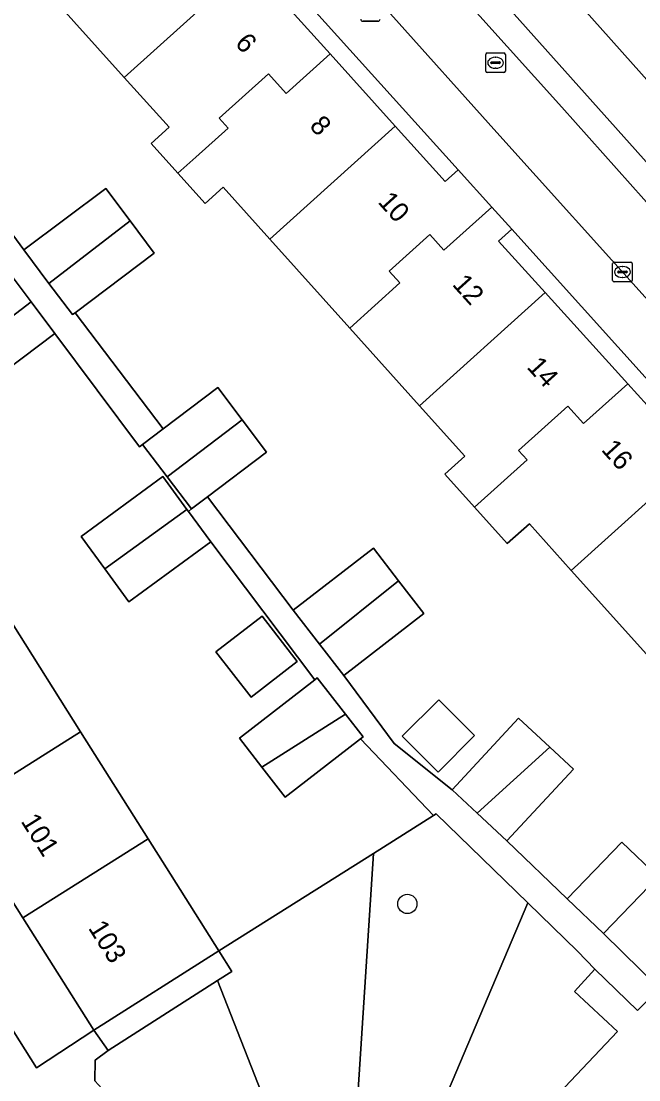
# Model space of a CAD drawing. Extents: x 162344 to 162869, y 381217 to 381818.
# Drawn here: x 162627.4 to 162658.9, y 381421.8 to 381475.8 of the extents above; entities that cross this region are included whole.
import ezdxf

# ---------------------------------------------------------------- set-up
doc = ezdxf.new("R2010")
doc.units = 0
for name, color, linetype in [('IMGEO_Boom', 7, 'Continuous'), ('IMGEO_Erf', 7, 'Continuous'), ('IMGEO_Groenvoorziening', 7, 'Continuous'), ('IMGEO_Kolk', 7, 'Continuous'), ('IMGEO_Lichtmast', 7, 'Continuous'), ('IMGEO_Pand', 7, 'Continuous'), ('IMGEO_Pand_nummerreeks', 7, 'Continuous'), ('IMGEO_Parkeervlak_open', 7, 'Continuous'), ('IMGEO_Rijbaan_lokaal_gesloten', 7, 'Continuous'), ('IMGEO_Rioolput', 7, 'Continuous'), ('IMGEO_Voetpad_open', 7, 'Continuous')]:
    doc.layers.add(name, color=color, linetype=linetype)

msp = doc.modelspace()

# ---------------------------------------------------------------- linework, layer by layer
at = {"layer": 'IMGEO_Boom'}
msp.add_circle((162647.119, 381430.789), 0.489, dxfattribs=at)
at = {"layer": 'IMGEO_Erf'}
for points in [[(162635.433, 381499.549), (162682.655, 381446.622)], [(162659.46, 381443.343), (162655.467, 381447.783), (162653.336, 381450.153), (162652.212, 381449.143), (162650.545, 381450.997), (162649.034, 381452.678), (162650.051, 381453.593), (162647.738, 381456.165), (162644.18, 381460.122), (162640.102, 381464.657), (162637.728, 381467.296), (162636.815, 381466.473), (162635.425, 381468.013), (162634.056, 381469.531), (162634.973, 381470.359), (162632.692, 381472.896), (162628.767, 381477.262)], [(162623.306, 381469.905), (162627.567, 381464.113), (162631.754, 381467.228), (162632.988, 381465.584), (162634.221, 381463.94), (162630.18, 381460.909), (162634.669, 381454.985), (162637.454, 381457.092), (162638.698, 381455.448), (162639.942, 381453.804), (162636.929, 381451.525), (162641.302, 381445.756), (162645.389, 381448.911), (162646.674, 381447.247), (162647.959, 381445.583), (162643.872, 381442.428), (162646.45, 381438.958), (162649.395, 381436.598), (162652.784, 381440.256), (162654.386, 381438.771), (162655.584, 381437.661), (162652.194, 381434.003), (162655.266, 381431.048), (162658.04, 381433.93), (162659.894, 381432.164), (162657.12, 381429.282), (162659.964, 381426.485)], [(162626.971, 381445.09), (162630.46, 381439.564), (162633.906, 381434.108), (162634.845, 381432.62), (162637.515, 381428.392), (162645.386, 381433.36), (162648.441, 381435.288), (162644.726, 381439.195), (162640.889, 381436.221), (162639.694, 381437.762), (162638.556, 381439.23), (162642.404, 381442.212), (162637.095, 381449.232), (162632.925, 381446.177), (162631.695, 381447.856), (162630.487, 381449.505), (162634.657, 381452.559), (162635.881, 381450.889), (162635.955, 381450.788), (162636.115, 381450.909), (162634.876, 381452.545), (162633.627, 381454.197), (162633.466, 381454.067), (162629.15, 381459.84), (162625.032, 381456.764)]]:
    msp.add_lwpolyline(points, dxfattribs=at)
for points in [[(162637.412, 381481.823), (162636.743, 381481.221), (162639.073, 381478.639), (162643.182, 381474.087), (162646.497, 381470.414), (162649.049, 381467.586), (162649.711, 381468.182)], [(162600.252, 381466.808), (162628.211, 381422.438), (162631.131, 381424.361), (162627.522, 381430.077), (162624.077, 381435.533), (162620.587, 381441.059), (162617.109, 381446.568), (162613.625, 381452.085), (162610.21, 381457.494), (162606.701, 381463.05), (162603.166, 381468.649)], [(162652.435, 381465.161), (162651.766, 381464.559), (162654.145, 381461.932), (162658.353, 381457.286), (162661.798, 381453.482), (162664.299, 381450.721), (162664.937, 381451.295)], [(162637.359, 381443.639), (162639.712, 381445.456), (162641.502, 381443.138), (162639.149, 381441.321)], [(162648.714, 381441.192), (162650.543, 381439.364), (162648.681, 381437.501), (162646.852, 381439.33)]]:
    msp.add_lwpolyline(points, close=True, dxfattribs=at)
at = {"layer": 'IMGEO_Groenvoorziening'}
for points in [[(162653.252, 381430.844), (162648.583, 381435.378), (162648.441, 381435.288), (162645.386, 381433.36), (162644.195, 381415.034)], [(162645.386, 381433.36), (162637.515, 381428.392), (162638.171, 381427.354), (162637.447, 381426.89), (162642.232, 381414.68)], [(162644.195, 381415.034), (162645.386, 381433.36)], [(162646.345, 381414.52), (162653.252, 381430.844)], [(162657.831, 381424.284), (162655.633, 381426.331), (162656.668, 381427.458), (162655.791, 381428.379), (162653.252, 381430.844), (162646.345, 381414.52)], [(162637.447, 381426.89), (162631.866, 381423.318), (162631.213, 381422.825), (162631.192, 381421.776), (162633.611, 381419.13), (162634.944, 381419.82), (162638.882, 381415.568), (162640.632, 381413.679)], [(162642.232, 381414.68), (162637.447, 381426.89)], [(162647.681, 381413.583), (162657.831, 381424.284)]]:
    msp.add_lwpolyline(points, dxfattribs=at)
at = {"layer": 'IMGEO_Kolk'}
for p, q in [((162657.58, 381462.556), (162657.58, 381463.408)), ((162657.655, 381463.482), (162658.507, 381463.482)), ((162658.068, 381463.262), (162658.093, 381463.262)), ((162658.581, 381463.408), (162658.581, 381462.556)), ((162657.839, 381462.976), (162657.839, 381462.988)), ((162658.277, 381462.939), (162657.879, 381462.939)), ((162657.882, 381463.025), (162658.28, 381463.025)), ((162658.091, 381462.702), (162658.066, 381462.702)), ((162658.323, 381462.988), (162658.323, 381462.976)), ((162658.507, 381462.482), (162657.655, 381462.482))]:
    msp.add_line(p, q, dxfattribs=at)
for points in [[(162657.58, 381462.556), (162657.58, 381463.408)], [(162657.655, 381463.482), (162658.507, 381463.482)], [(162658.581, 381463.408), (162658.581, 381462.556)], [(162658.507, 381462.482), (162657.655, 381462.482)]]:
    msp.add_lwpolyline(points, dxfattribs=at)
for centre, radius, start, end in [((162657.657, 381463.406), 0.0765, 91.552, 178.448), ((162657.657, 381463.406), 0.0765, 91.552, 178.448), ((162658.505, 381463.406), 0.0765, 1.552, 88.448), ((162658.505, 381463.406), 0.0765, 1.552, 88.448), ((162657.657, 381462.558), 0.0765, 181.552, 268.448), ((162657.657, 381462.558), 0.0765, 181.552, 268.448), ((162657.879, 381462.985), 0.0403, 85.8775, 175.7526), ((162657.876, 381462.975), 0.0366, 178.938, 274.7102), ((162658.28, 381462.982), 0.043, 264.8664, 352.4533), ((162658.284, 381462.987), 0.0386, 1.7309, 96.639), ((162658.505, 381462.558), 0.0765, 271.552, 358.448), ((162658.505, 381462.558), 0.0765, 271.552, 358.448)]:
    msp.add_arc(centre, radius, start, end, dxfattribs=at)
for centre, major_axis, ratio, start_param, end_param in [((162658.067, 381462.982), (-0.387, 0.002), 0.722429, 4.712389, 7.853982), ((162658.092, 381462.982), (-0.39, 0.002), 0.717154, 1.570796, 4.712389)]:
    msp.add_ellipse(centre, major_axis=major_axis, ratio=ratio, start_param=start_param, end_param=end_param, dxfattribs=at)
at = {"layer": 'IMGEO_Lichtmast'}
for p, q in [((162645.63, 381475.758), (162644.84, 381475.758)), ((162644.84, 381475.758), (162645.63, 381475.758))]:
    msp.add_line(p, q, dxfattribs=at)
for centre, start, end in [((162644.84, 381475.858), 180, 270), ((162644.84, 381475.858), 180, 270), ((162645.63, 381475.858), 270, 0), ((162645.63, 381475.858), 270, 0)]:
    msp.add_arc(centre, 0.1, start, end, dxfattribs=at)
at = {"layer": 'IMGEO_Pand'}
for points in [[(162628.767, 381477.262), (162632.692, 381472.896), (162639.073, 381478.639), (162636.743, 381481.221), (162637.412, 381481.823), (162635.981, 381483.41), (162633.538, 381481.207), (162632.82, 381482.003), (162630.756, 381480.142), (162631.297, 381479.542)], [(162643.182, 381474.087), (162639.073, 381478.639), (162632.692, 381472.896), (162634.973, 381470.359), (162634.056, 381469.531), (162635.425, 381468.013), (162636.341, 381468.839), (162637.977, 381470.315), (162637.529, 381470.812), (162640.038, 381473.074), (162640.944, 381472.069)], [(162643.182, 381474.087), (162640.944, 381472.069), (162640.038, 381473.074), (162637.529, 381470.812), (162637.977, 381470.315), (162636.341, 381468.839), (162635.425, 381468.013), (162636.815, 381466.473), (162637.728, 381467.296), (162640.102, 381464.657), (162646.497, 381470.414)], [(162646.497, 381470.414), (162640.102, 381464.657), (162644.18, 381460.122), (162646.732, 381462.422), (162646.191, 381463.022), (162648.255, 381464.883), (162648.973, 381464.087), (162651.417, 381466.29), (162649.711, 381468.182), (162649.049, 381467.586)], [(162632.988, 381465.584), (162631.754, 381467.228), (162627.567, 381464.113), (162628.854, 381462.4)], [(162654.145, 381461.932), (162651.766, 381464.559), (162652.435, 381465.161), (162651.417, 381466.29), (162648.973, 381464.087), (162648.255, 381464.883), (162646.191, 381463.022), (162646.732, 381462.422), (162644.18, 381460.122), (162647.738, 381456.165)], [(162632.988, 381465.584), (162628.854, 381462.4), (162630.047, 381460.809), (162630.18, 381460.909), (162634.221, 381463.94)], [(162627.939, 381461.461), (162626.727, 381463.083), (162622.609, 381460.007), (162623.851, 381458.345)], [(162629.15, 381459.84), (162627.939, 381461.461), (162623.851, 381458.345), (162625.032, 381456.764)], [(162650.545, 381450.997), (162653.22, 381453.408), (162652.785, 381453.891), (162655.294, 381456.153), (162656.102, 381455.257), (162658.353, 381457.286), (162654.145, 381461.932), (162647.738, 381456.165), (162650.051, 381453.593), (162649.034, 381452.678)], [(162650.545, 381450.997), (162652.212, 381449.143), (162653.336, 381450.153), (162655.467, 381447.783), (162661.798, 381453.482), (162658.353, 381457.286), (162656.102, 381455.257), (162655.294, 381456.153), (162652.785, 381453.891), (162653.22, 381453.408)], [(162638.698, 381455.448), (162637.454, 381457.092), (162634.669, 381454.985), (162633.627, 381454.197), (162634.876, 381452.545)], [(162638.698, 381455.448), (162634.876, 381452.545), (162636.115, 381450.909), (162636.929, 381451.525), (162639.942, 381453.804)], [(162666.613, 381449.436), (162664.937, 381451.295), (162664.299, 381450.721), (162661.798, 381453.482), (162655.467, 381447.783), (162659.46, 381443.343), (162661.928, 381445.567), (162661.387, 381446.167), (162663.451, 381448.028), (162664.169, 381447.232)], [(162635.881, 381450.889), (162634.657, 381452.559), (162630.487, 381449.505), (162631.695, 381447.856)], [(162637.095, 381449.232), (162635.955, 381450.788), (162635.881, 381450.889), (162631.695, 381447.856), (162632.925, 381446.177)], [(162646.674, 381447.247), (162645.389, 381448.911), (162641.302, 381445.756), (162642.637, 381444.027)], [(162646.674, 381447.247), (162642.637, 381444.027), (162643.872, 381442.428), (162647.959, 381445.583)], [(162637.359, 381443.639), (162639.149, 381441.321), (162641.502, 381443.138), (162639.712, 381445.456)], [(162630.46, 381439.564), (162626.971, 381445.09), (162620.587, 381441.059), (162624.077, 381435.533)], [(162643.96, 381440.457), (162642.526, 381442.307), (162642.404, 381442.212), (162638.556, 381439.23), (162639.694, 381437.762)], [(162646.852, 381439.33), (162648.681, 381437.501), (162650.543, 381439.364), (162648.714, 381441.192)], [(162644.726, 381439.195), (162644.859, 381439.298), (162643.96, 381440.457), (162639.694, 381437.762), (162640.889, 381436.221)], [(162650.667, 381435.419), (162654.386, 381438.771), (162652.784, 381440.256), (162649.395, 381436.598)], [(162630.46, 381439.564), (162624.077, 381435.533), (162627.522, 381430.077), (162633.906, 381434.108)], [(162650.667, 381435.419), (162652.194, 381434.003), (162655.584, 381437.661), (162654.386, 381438.771)], [(162627.522, 381430.077), (162631.131, 381424.361), (162637.515, 381428.392), (162634.845, 381432.62), (162633.906, 381434.108)], [(162657.12, 381429.282), (162659.894, 381432.164), (162658.04, 381433.93), (162655.266, 381431.048)]]:
    msp.add_lwpolyline(points, close=True, dxfattribs=at)
at = {"layer": 'IMGEO_Parkeervlak_open'}
for points in [[(162661.975, 381464.068), (162662.73, 381464.743), (162633.504, 381497.442)], [(162632.206, 381496.785), (162637.045, 381491.405), (162645.092, 381482.381), (162654.995, 381471.374), (162661.949, 381463.568)]]:
    msp.add_lwpolyline(points, dxfattribs=at)
at = {"layer": 'IMGEO_Rijbaan_lokaal_gesloten'}
msp.add_lwpolyline([(162645.092, 381482.381), (162637.045, 381491.405), (162632.206, 381496.785), (162632.112, 381496.894), (162629.654, 381494.622), (162629.754, 381494.514), (162640.833, 381482.197), (162651.674, 381470.086), (162659.547, 381461.359), (162659.702, 381461.185), (162662.119, 381463.377), (162661.949, 381463.568), (162654.995, 381471.374)], close=True, dxfattribs=at)
at = {"layer": 'IMGEO_Rioolput'}
for p, q in [((162651.11, 381473.213), (162651.11, 381474.065)), ((162651.185, 381474.139), (162652.037, 381474.139)), ((162651.598, 381473.919), (162651.623, 381473.919)), ((162652.111, 381474.065), (162652.111, 381473.213)), ((162651.369, 381473.633), (162651.369, 381473.645)), ((162651.807, 381473.596), (162651.409, 381473.596)), ((162651.412, 381473.682), (162651.81, 381473.682)), ((162651.621, 381473.359), (162651.596, 381473.359)), ((162651.853, 381473.645), (162651.853, 381473.633)), ((162652.037, 381473.139), (162651.185, 381473.139))]:
    msp.add_line(p, q, dxfattribs=at)
for points in [[(162651.11, 381473.213), (162651.11, 381474.065)], [(162651.185, 381474.139), (162652.037, 381474.139)], [(162652.111, 381474.065), (162652.111, 381473.213)], [(162652.037, 381473.139), (162651.185, 381473.139)]]:
    msp.add_lwpolyline(points, dxfattribs=at)
for centre, radius, start, end in [((162651.187, 381474.063), 0.0765, 91.552, 178.448), ((162651.187, 381474.063), 0.0765, 91.552, 178.448), ((162652.035, 381474.063), 0.0765, 1.552, 88.448), ((162652.035, 381474.063), 0.0765, 1.552, 88.448), ((162651.409, 381473.642), 0.0403, 85.8775, 175.7526), ((162651.406, 381473.632), 0.0366, 178.938, 274.7102), ((162651.81, 381473.639), 0.043, 264.8664, 352.4533), ((162651.814, 381473.644), 0.0386, 1.7309, 96.639), ((162651.187, 381473.215), 0.0765, 181.552, 268.448), ((162651.187, 381473.215), 0.0765, 181.552, 268.448), ((162652.035, 381473.215), 0.0765, 271.552, 358.448), ((162652.035, 381473.215), 0.0765, 271.552, 358.448)]:
    msp.add_arc(centre, radius, start, end, dxfattribs=at)
for centre, major_axis, ratio, start_param, end_param in [((162651.597, 381473.639), (-0.387, 0.002), 0.722429, 4.712389, 7.853982), ((162651.622, 381473.639), (-0.39, 0.002), 0.717154, 1.570796, 4.712389)]:
    msp.add_ellipse(centre, major_axis=major_axis, ratio=ratio, start_param=start_param, end_param=end_param, dxfattribs=at)
at = {"layer": 'IMGEO_Voetpad_open'}
for points in [[(162674.935, 381444.16), (162670.743, 381448.931), (162668.09, 381451.805), (162661.728, 381458.92), (162659.702, 381461.185), (162659.547, 381461.359), (162651.674, 381470.086), (162640.833, 381482.197), (162629.754, 381494.514), (162629.654, 381494.622), (162624.682, 381500), (162623.472, 381501.309), (162622.948, 381500.954), (162621.74, 381502.2), (162621.398, 381501.874), (162621.057, 381502.239), (162618.756, 381500), (162617.995, 381499.26), (162617.432, 381498.758)], [(162617.48, 381497.935), (162619.438, 381495.925), (162623.107, 381499.381), (162627.975, 381494.211), (162624.32, 381490.769), (162624.818, 381489.816), (162625.117, 381489.484), (162627.423, 381491.558), (162628.17, 381492.223), (162634.659, 381484.876), (162635.981, 381483.41), (162637.412, 381481.823), (162649.711, 381468.182), (162651.417, 381466.29), (162652.435, 381465.161), (162664.937, 381451.295), (162666.613, 381449.436), (162667.63, 381448.308), (162674.063, 381441.248)], [(162682.655, 381446.622), (162635.433, 381499.549)], [(162632.873, 381496.892), (162633.504, 381497.442), (162662.73, 381464.743), (162661.975, 381464.068)], [(162634.944, 381419.82), (162633.611, 381419.13), (162631.192, 381421.776), (162631.213, 381422.825), (162631.866, 381423.318), (162631.131, 381424.361), (162628.211, 381422.438), (162600.252, 381466.808), (162603.166, 381468.649), (162608.933, 381472.289), (162607.642, 381473.555), (162606.858, 381474.324), (162602.378, 381479.081), (162599.95, 381481.55)], [(162614.124, 381479.21), (162618.804, 381473.616), (162620.067, 381471.947), (162621.329, 381470.279), (162626.727, 381463.083), (162627.939, 381461.461), (162629.15, 381459.84), (162633.466, 381454.067), (162633.627, 381454.197), (162634.669, 381454.985), (162630.18, 381460.909), (162630.047, 381460.809), (162628.854, 381462.4), (162627.567, 381464.113), (162623.306, 381469.905), (162622.081, 381471.537), (162620.826, 381473.208), (162615.133, 381480.569)], [(162674.119, 381440.758), (162673.628, 381440.312), (162671.27, 381438.216), (162671.535, 381437.917), (162669.781, 381436.377), (162669.525, 381436.657), (162667.366, 381434.744), (162667.609, 381434.502), (162659.964, 381426.485), (162658.852, 381425.353), (162656.668, 381427.458), (162655.633, 381426.331), (162657.831, 381424.284), (162647.681, 381413.583), (162645.709, 381411.504), (162644.16, 381409.871), (162646.035, 381407.328), (162654.69, 381416.499), (162662.167, 381424.432)]]:
    msp.add_lwpolyline(points, dxfattribs=at)
for points in [[(162646.45, 381438.958), (162643.872, 381442.428), (162642.637, 381444.027), (162641.302, 381445.756), (162636.929, 381451.525), (162636.115, 381450.909), (162635.955, 381450.788), (162637.095, 381449.232), (162642.404, 381442.212), (162642.526, 381442.307), (162643.96, 381440.457), (162644.859, 381439.298), (162644.726, 381439.195), (162648.441, 381435.288), (162648.583, 381435.378), (162653.252, 381430.844), (162655.791, 381428.379), (162656.668, 381427.458), (162658.852, 381425.353), (162659.964, 381426.485), (162657.12, 381429.282), (162655.266, 381431.048), (162652.194, 381434.003), (162650.667, 381435.419), (162649.395, 381436.598)], [(162631.131, 381424.361), (162631.866, 381423.318), (162637.447, 381426.89), (162638.171, 381427.354), (162637.515, 381428.392)]]:
    msp.add_lwpolyline(points, close=True, dxfattribs=at)

# ---------------------------------------------------------------- texts
at = {"layer": 'IMGEO_Pand_nummerreeks'}
for s, rotation, p in [('6', 312.0549, (162638.289, 381474.602)), ('8', 312.0549, (162642.086, 381470.392)), ('10', 312.0558, (162645.574, 381466.527)), ('12', 312.0558, (162649.365, 381462.326)), ('14', 312.0558, (162653.162, 381458.116)), ('16', 312.0558, (162656.957, 381453.909)), ('101', 302.2698, (162627.392, 381435.003)), ('103', 302.2698, (162630.826, 381429.563))]:
    msp.add_text(s, height=1, rotation=rotation, dxfattribs=at).set_placement(p)

doc.saveas('drawing.dxf')
